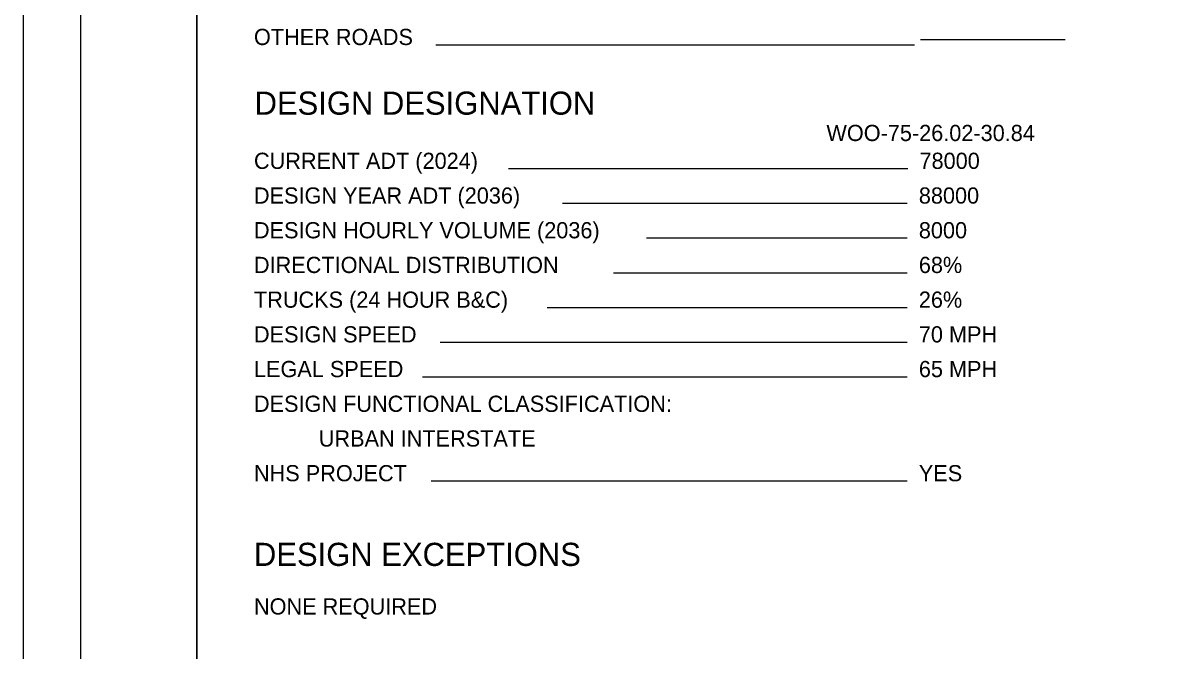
# Model space of a CAD drawing. Extents: x 0 to 34, y 0 to 22.
# Drawn here: x 0 to 9.95, y 5.64 to 11.07 of the extents above; entities that cross this region are included whole.
import ezdxf

# ---------------------------------------------------------------- set-up
doc = ezdxf.new("R2010")
doc.units = 0
for name, color, linetype in [('SH_Border', 7, 'Continuous'), ('SH_Cut_Line', 7, 'Continuous'), ('SH_Data', 7, 'Continuous'), ('SH_Text', 7, 'Continuous')]:
    doc.layers.add(name, color=color, linetype=linetype)

msp = doc.modelspace()

# ---------------------------------------------------------------- linework, layer by layer
at = {"layer": 'SH_Border'}
for points in [[(0.5, 21.5), (1.5, 21.5), (1.5, 0.5), (0.5, 0.5)], [(1.5, 21.5), (33.5, 21.5), (33.5, 0.5), (1.5, 0.5)]]:
    msp.add_lwpolyline(points, close=True, dxfattribs=at)
at = {"layer": 'SH_Cut_Line'}
msp.add_lwpolyline([(0, 0), (34, 0), (34, 22), (0, 22)], close=True, dxfattribs=at)
at = {"layer": 'SH_Data'}
for p, q in [((7.7, 10.8767), (3.5657, 10.8767)), ((9, 10.9223), (7.75, 10.9223)), ((7.6424, 9.8062), (4.1936, 9.8062)), ((7.6368, 9.5062), (4.6592, 9.5062)), ((7.6368, 9.2062), (5.3852, 9.2062)), ((7.6368, 8.9062), (5.0988, 8.9062)), ((7.6368, 8.6062), (4.5259, 8.6062)), ((7.6368, 8.3062), (3.6035, 8.3062)), ((7.6368, 8.0062), (3.4488, 8.0062)), ((7.6368, 7.1062), (3.5243, 7.1062))]:
    msp.add_line(p, q, dxfattribs=at)

# ---------------------------------------------------------------- texts
msp.add_text('DESIGN DESIGNATION', height=0.2, dxfattribs=at).set_placement((2, 10.2747))
at = {"layer": 'SH_Text'}
for s, height, p in [('OTHER ROADS', 0.14, (1.9944, 10.8767)), ('WOO-75-26.02-30.84', 0.14, (6.9386, 10.0469)), ('CURRENT ADT (2024)', 0.14, (1.9944, 9.8062)), ('78000', 0.14, (7.7424, 9.8062)), ('DESIGN YEAR ADT (2036)', 0.14, (1.9944, 9.5062)), ('88000', 0.14, (7.7368, 9.5062)), ('DESIGN HOURLY VOLUME (2036)', 0.14, (1.9944, 9.2062)), ('8000', 0.14, (7.7368, 9.2062)), ('DIRECTIONAL DISTRIBUTION', 0.14, (1.9944, 8.9062)), ('68%', 0.14, (7.7368, 8.9062)), ('TRUCKS (24 HOUR B&C)', 0.14, (1.9944, 8.6062)), ('26%', 0.14, (7.7368, 8.6062)), ('DESIGN SPEED', 0.14, (1.9944, 8.3062)), ('70 MPH', 0.14, (7.7368, 8.3062)), ('LEGAL SPEED', 0.14, (1.9944, 8.0062)), ('65 MPH', 0.14, (7.7368, 8.0062)), ('DESIGN FUNCTIONAL CLASSIFICATION:', 0.14, (1.9944, 7.7062)), ('URBAN INTERSTATE', 0.14, (2.5544, 7.4062)), ('NHS PROJECT', 0.14, (1.9944, 7.1062)), ('YES', 0.14, (7.7368, 7.1062)), ('DESIGN EXCEPTIONS', 0.2, (1.9944, 6.3744)), ('NONE REQUIRED', 0.14, (1.9944, 5.9544))]:
    msp.add_text(s, height=height, dxfattribs=at).set_placement(p)

doc.saveas('drawing.dxf')
